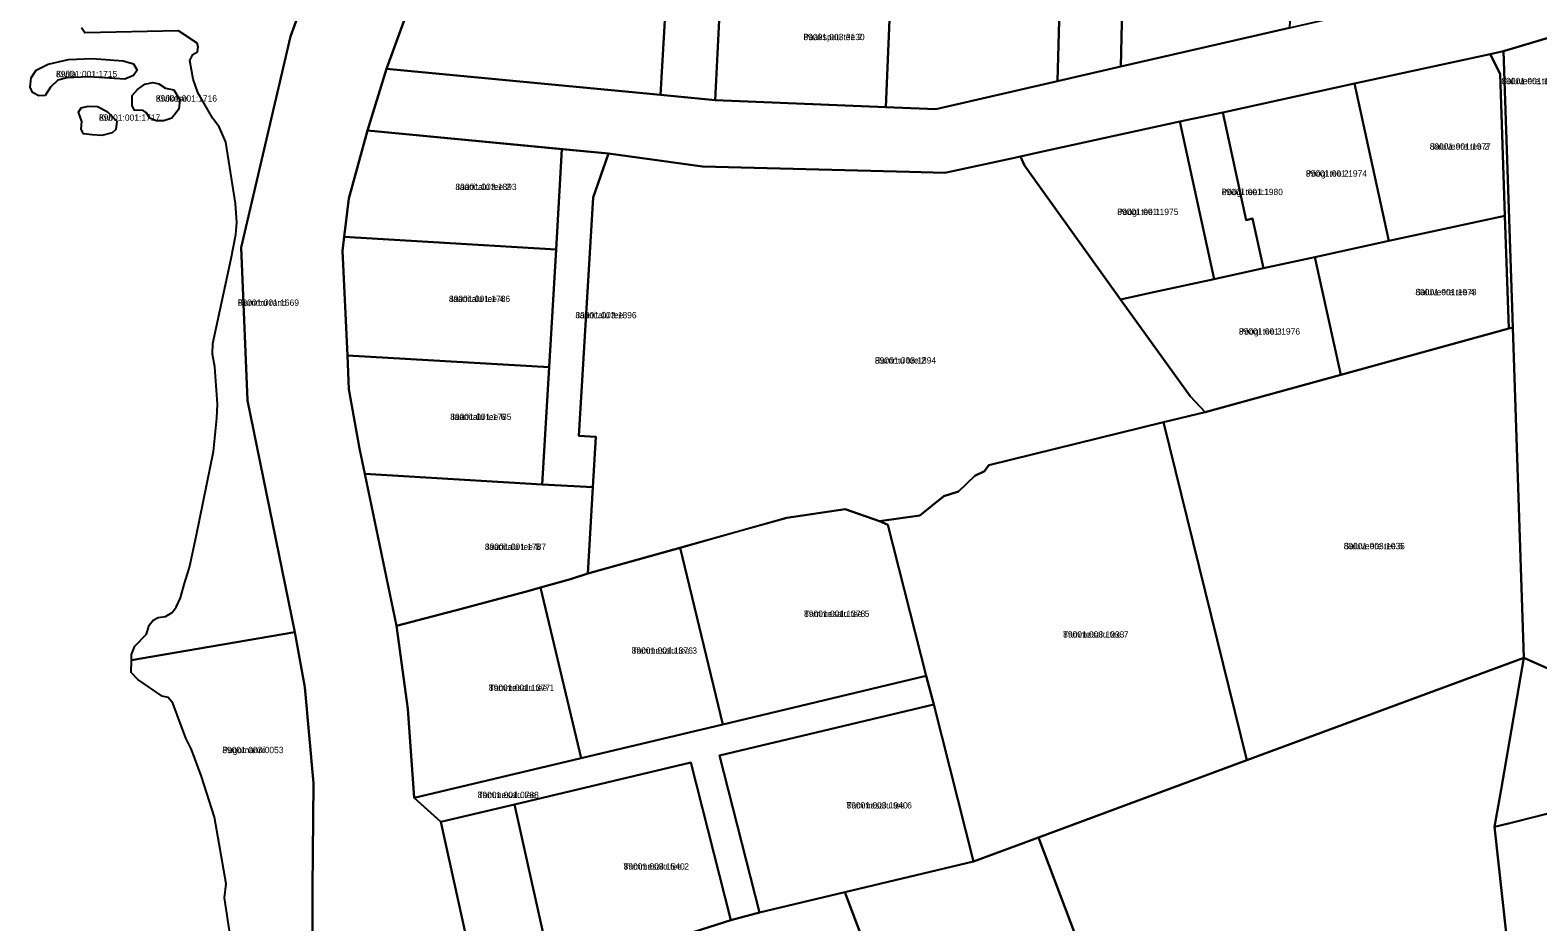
# Model space of a CAD drawing. Extents: x 526849 to 562296, y 6591741 to 6618546.
# Drawn here: x 544809.7 to 545167, y 6599914.9 to 6600126.2 of the extents above; entities that cross this region are included whole.
import ezdxf

# ---------------------------------------------------------------- set-up
doc = ezdxf.new("R2010")
doc.units = 0
for name, color, linetype in [('L_AADRESS', 7, 'Continuous'), ('PIIR', 7, 'Continuous'), ('TUNNUS', 7, 'Continuous')]:
    doc.layers.add(name, color=color, linetype=linetype)

msp = doc.modelspace()

# ---------------------------------------------------------------- linework, layer by layer
at = {"layer": 'PIIR'}
for points in [[(544935.9, 6600383.02), (544936.98, 6600367.84), (544936.01, 6600333.58), (544927.16, 6600282.9), (544924.54, 6600267.87), (544924.07, 6600264.18), (544923.97, 6600229.25), (544922.74, 6600211.91), (544921.23, 6600191.36), (544905.93, 6600149.36), (544894.17, 6600117.06), (544889.67, 6600102.41), (544885.27, 6600086.32), (544884.12, 6600077.21), (544883.73, 6600073.86), (544884.89, 6600049.11), (544885.24, 6600041.15), (544887.74, 6600027.04), (544889.02, 6600021.07), (544896.56, 6599985.02), (544899.19, 6599965.34), (544900.74, 6599944.25), (544907, 6599938.56), (544916.15, 6599897.4)], [(544876.63, 6599889.78), (544876.64, 6599922.84), (544876.87, 6599947.77), (544874.78, 6599970.54), (544872.43, 6599983.5), (544861.21, 6600038.43), (544859.69, 6600074.67), (544871.4, 6600124.69), (544896.35, 6600193.26), (544898.82, 6600204.02), (544900.09, 6600216.66), (544899.91, 6600234.86), (544900.08, 6600265.75), (544903.2, 6600290.48), (544911.64, 6600322.51), (544913.02, 6600327.74), (544914.27, 6600338.7), (544913.97, 6600348.15), (544914.61, 6600362.18), (544913.58, 6600371.54), (544912.98, 6600377.11)], [(544896.35, 6600193.26), (544871.4, 6600124.69), (544859.69, 6600074.67), (544861.21, 6600038.43), (544872.43, 6599983.5), (544838.29, 6599977.71), (544833.69, 6599976.93), (544833.72, 6599978.26), (544834.51, 6599980.25), (544837.29, 6599983.1), (544837.92, 6599985.17), (544838.87, 6599986.36), (544840.06, 6599986.99), (544841.81, 6599987.23), (544843.4, 6599988.18), (544844.35, 6599989.45), (544845.38, 6599991.68), (544846.19, 6599994.86), (544847.42, 6599998.61), (544847.72, 6600000), (544849.15, 6600006.57), (544853.2, 6600026.36), (544853.96, 6600034.22), (544854.11, 6600037.56), (544853.48, 6600046.45), (544852.92, 6600049.38), (544853, 6600051.92), (544857.37, 6600072.08), (544858.48, 6600077.8), (544858.72, 6600080.58), (544858.4, 6600085.1), (544856.1, 6600099.63), (544854.51, 6600103.28), (544853, 6600105.26), (544849.43, 6600111.45), (544848.32, 6600114.55), (544847.59, 6600119.02), (544848.24, 6600120.42), (544849.35, 6600121.06), (544849.54, 6600122.2), (544849.27, 6600123.12), (544844.89, 6600126.01), (544822.68, 6600125.58), (544821.89, 6600126.77)], [(545173.74, 6600125.66), (545158.87, 6600121.22), (545155.76, 6600120.51), (545123.56, 6600113.52), (545092.36, 6600106.67), (545082.18, 6600104.51), (545049.29, 6600097.33), (545044.38, 6600096.26), (545041.16, 6600095.54), (545026.52, 6600092.35), (545018.1, 6600092.58), (544969.05, 6600093.91), (544946.8, 6600096.96), (544889.67, 6600102.41), (544894.17, 6600117.06), (544959.09, 6600110.88), (544972.03, 6600109.6), (545012.53, 6600107.93), (545024.34, 6600107.45), (545053.15, 6600114.08), (545068.19, 6600117.54), (545108.15, 6600126.72), (545160.88, 6600138.83), (545175.72, 6600145.39)], [(544857.61, 6599908.57), (544855.78, 6599920.56), (544856.18, 6599923.89), (544853.4, 6599939.69), (544850.3, 6599949.37), (544847.92, 6599955.72), (544846.57, 6599958.42), (544843.56, 6599966.75), (544842.45, 6599968.02), (544841.02, 6599968.34), (544835.22, 6599972.31), (544833.64, 6599973.98), (544833.69, 6599976.93), (544838.29, 6599977.71), (544872.43, 6599983.5), (544874.78, 6599970.54), (544876.87, 6599947.77), (544876.64, 6599922.84), (544876.63, 6599889.78)]]:
    msp.add_lwpolyline(points, dxfattribs=at)
for points in [[(544972.6, 6600265.88), (544983.04, 6600265.45), (544981.4, 6600229.66), (544979.63, 6600219.47), (544978.27, 6600219.55), (544976.21, 6600199.58), (544974.5, 6600168.56), (544973.54, 6600139.7), (544972.03, 6600109.6), (544959.09, 6600110.88), (544960.3, 6600131.26), (544961.35, 6600141.21), (544964.46, 6600170.57), (544967.18, 6600195.94), (544970.94, 6600229.71)], [(545059.58, 6600262.28), (545072.57, 6600261.74), (545071, 6600222.28), (545069.84, 6600192.45), (545069.19, 6600162.44), (545068.19, 6600117.54), (545053.15, 6600114.08), (545054.08, 6600145.79), (545055.59, 6600174.95), (545056.79, 6600203.98), (545058.23, 6600232.66)], [(545109.76, 6600160.72), (545108.15, 6600126.72), (545068.19, 6600117.54), (545069.19, 6600162.44)], [(544905.93, 6600149.36), (544961.35, 6600141.21), (544960.3, 6600131.26), (544959.09, 6600110.88), (544894.17, 6600117.06)], [(545053.15, 6600114.08), (545024.34, 6600107.45), (545012.53, 6600107.93), (545013.8, 6600138.16), (545014.33, 6600147.56), (545054.08, 6600145.79)], [(544973.54, 6600139.7), (545013.8, 6600138.16), (545012.53, 6600107.93), (544972.03, 6600109.6)], [(545158.87, 6600121.22), (545173.74, 6600125.66), (545174.9, 6600091.74), (545176.13, 6600056.08), (545177.11, 6600026.68), (545179.03, 6599970.68), (545163.73, 6599977.48), (545161.07, 6600055.74)], [(544810.28, 6600111.45), (544809.71, 6600112.65), (544809.98, 6600114.92), (544811.16, 6600116.7), (544813.95, 6600118.12), (544818.82, 6600119.25), (544824.4, 6600119.48), (544831.73, 6600118.9), (544834.18, 6600118.2), (544835.11, 6600116.7), (544834.18, 6600115.44), (544832.18, 6600114.56), (544828.48, 6600114.83), (544823.6, 6600115.15), (544818.44, 6600114.89), (544816.28, 6600114.35), (544814.52, 6600112.65), (544813.23, 6600110.71), (544811.77, 6600110.62)], [(545131.72, 6600076.29), (545123.56, 6600113.52), (545155.76, 6600120.51), (545158.06, 6600115.86), (545159.23, 6600082.23)], [(545158.06, 6600115.86), (545155.76, 6600120.51), (545158.87, 6600121.22), (545161.07, 6600055.74), (545160.11, 6600055.48), (545159.23, 6600082.23)], [(544833.88, 6600110.7), (544835.12, 6600112.15), (544836.87, 6600113.4), (544838.79, 6600113.8), (544840.17, 6600113.48), (544841.77, 6600112.44), (544843.78, 6600112.08), (544845.15, 6600109.71), (544844.96, 6600107.43), (544843.32, 6600105.34), (544841.41, 6600104.71), (544839.59, 6600104.71), (544838.08, 6600105.34), (544837.21, 6600106.68), (544836.46, 6600107.18), (544834.43, 6600107.25), (544833.87, 6600108.25)], [(545097.9, 6600081.19), (545092.36, 6600106.67), (545123.56, 6600113.52), (545131.72, 6600076.29), (545114.14, 6600072.43), (545102.02, 6600069.8), (545099.42, 6600081.55)], [(544828, 6600106.93), (544830.22, 6600104.63), (544829.98, 6600102.64), (544829.11, 6600101.85), (544826.73, 6600101.21), (544824.43, 6600101.37), (544822.38, 6600101.61), (544821.83, 6600102.69), (544821.97, 6600104.55), (544821.17, 6600106.77), (544821.81, 6600107.8), (544823.48, 6600108.2), (544825.7, 6600108.12)], [(545045.39, 6600094.12), (545044.38, 6600096.26), (545049.29, 6600097.33), (545082.18, 6600104.51), (545090.29, 6600067.18), (545076.33, 6600064.17), (545068.14, 6600062.4)], [(545090.29, 6600067.18), (545082.18, 6600104.51), (545092.36, 6600106.67), (545097.9, 6600081.19), (545099.42, 6600081.55), (545102.02, 6600069.8)], [(544889.67, 6600102.41), (544935.74, 6600098.02), (544934.35, 6600074.23), (544884.12, 6600077.21), (544885.27, 6600086.32)], [(544935.74, 6600098.02), (544946.8, 6600096.96), (544943.12, 6600086.51), (544939.77, 6600030.06), (544943.76, 6600029.83), (544943.06, 6600017.87), (544931.08, 6600018.55), (544932.74, 6600046.33), (544934.35, 6600074.23)], [(544946.8, 6600096.96), (544969.05, 6600093.91), (545018.1, 6600092.58), (545026.52, 6600092.35), (545041.16, 6600095.54), (545044.38, 6600096.26), (545045.39, 6600094.12), (545068.14, 6600062.4), (545084.6, 6600039.45), (545088.16, 6600035.68), (545078.29, 6600033.29), (545036.92, 6600023.1), (545035.88, 6600021.65), (545033.59, 6600020.62), (545029.7, 6600016.84), (545026.23, 6600015.78), (545020.57, 6600011.2), (545011.01, 6600009.83), (545002.86, 6600012.65), (544989.06, 6600010.64), (544977.25, 6600007.35), (544941.84, 6599997.41), (544943.06, 6600017.87), (544943.76, 6600029.83), (544939.77, 6600030.06), (544943.12, 6600086.51)], [(545120.32, 6600044.52), (545114.14, 6600072.43), (545131.72, 6600076.29), (545159.23, 6600082.23), (545160.11, 6600055.48)], [(544883.73, 6600073.86), (544884.12, 6600077.21), (544934.35, 6600074.23), (544932.74, 6600046.33), (544884.89, 6600049.11)], [(545084.6, 6600039.45), (545068.14, 6600062.4), (545076.33, 6600064.17), (545090.29, 6600067.18), (545102.02, 6600069.8), (545114.14, 6600072.43), (545120.32, 6600044.52), (545088.16, 6600035.68)], [(545098.04, 6599953.21), (545078.29, 6600033.29), (545088.16, 6600035.68), (545120.32, 6600044.52), (545160.11, 6600055.48), (545161.07, 6600055.74), (545163.73, 6599977.48)], [(544885.24, 6600041.15), (544884.89, 6600049.11), (544932.74, 6600046.33), (544931.08, 6600018.55), (544889.02, 6600021.07), (544887.74, 6600027.04)], [(545011.01, 6600009.83), (545020.57, 6600011.2), (545026.23, 6600015.78), (545029.7, 6600016.84), (545033.59, 6600020.62), (545035.88, 6600021.65), (545036.92, 6600023.1), (545078.29, 6600033.29), (545098.04, 6599953.21), (545048.68, 6599934.92), (545033.29, 6599929.2), (545023.84, 6599966.37), (545022.08, 6599973.18), (545012.98, 6600008.97)], [(544896.56, 6599985.02), (544889.02, 6600021.07), (544931.08, 6600018.55), (544943.06, 6600017.87), (544941.84, 6599997.41), (544937.79, 6599996.12), (544930.63, 6599994.14), (544928.23, 6599993.4), (544911.93, 6599989.08)], [(544973.89, 6599961.68), (544963.75, 6600003.56), (544977.25, 6600007.36), (544989.06, 6600010.64), (545002.86, 6600012.65), (545011.01, 6600009.83), (545012.98, 6600008.97), (545022.08, 6599973.18)], [(544940.27, 6599953.66), (544930.63, 6599994.14), (544937.79, 6599996.12), (544941.84, 6599997.41), (544963.75, 6600003.56), (544973.89, 6599961.68)], [(545163.73, 6599977.48), (545179.03, 6599970.68), (545209.11, 6599978.82), (545238.57, 6599986.81), (545286.6, 6599999.81), (545305.47, 6600004.91), (545311.04, 6599975.66), (545278.78, 6599967.84), (545237.86, 6599957.57), (545198.15, 6599947.78), (545173.86, 6599941.68), (545160.35, 6599938.29), (545156.74, 6599937.39), (545158.3, 6599946.25)], [(544899.19, 6599965.34), (544896.56, 6599985.02), (544911.93, 6599989.08), (544928.23, 6599993.4), (544930.63, 6599994.14), (544940.27, 6599953.66), (544900.74, 6599944.25)], [(545048.68, 6599934.92), (545098.04, 6599953.21), (545163.73, 6599977.48), (545158.3, 6599946.25), (545156.74, 6599937.39), (545160.42, 6599904.41), (545163.99, 6599869.22), (545161.45, 6599868.56), (545081.67, 6599847.54)], [(544900.74, 6599944.25), (544940.27, 6599953.66), (544973.89, 6599961.68), (545022.08, 6599973.18), (545023.84, 6599966.37), (544973.07, 6599954.3), (544982.54, 6599917.15), (544975.8, 6599915.26), (544966.29, 6599952.67), (544924.51, 6599942.73), (544907, 6599938.56)], [(545023.84, 6599966.37), (545033.29, 6599929.2), (545002.78, 6599921.96), (544982.54, 6599917.15), (544973.07, 6599954.3)], [(544924.51, 6599942.73), (544966.29, 6599952.67), (544975.8, 6599915.26), (544933.6, 6599901.88)], [(545162.53, 6599904.57), (545160.42, 6599904.41), (545156.74, 6599937.38), (545160.36, 6599938.3), (545173.85, 6599941.7), (545198.15, 6599947.78), (545200.27, 6599938.7), (545203.83, 6599924.23), (545202.98, 6599911.58), (545175.09, 6599906.71)], [(544916.15, 6599897.4), (544907, 6599938.56), (544924.51, 6599942.73), (544933.6, 6599901.88), (544931.26, 6599901), (544929.8, 6599900.53), (544918.55, 6599897.89), (544921.36, 6599885.81), (544917.9, 6599884.75), (544919.81, 6599874.06), (544919.82, 6599871.95), (544934.83, 6599839.1), (544920.65, 6599833.6), (544910.88, 6599852.47), (544904.1, 6599849.41), (544900.98, 6599856.98), (544903.72, 6599858.18), (544902.51, 6599867.16), (544901.34, 6599894.22)], [(545002.78, 6599921.96), (545033.29, 6599929.2), (545048.68, 6599934.92), (545081.67, 6599847.54), (545055.54, 6599840.63), (545050.31, 6599868.18), (545049.26, 6599873.69), (545023.71, 6599866.51)], [(544931.26, 6599901), (544933.6, 6599901.88), (544975.8, 6599915.26), (544982.54, 6599917.15), (545002.78, 6599921.96), (545023.71, 6599866.51), (544977.36, 6599849.1), (544967.71, 6599875.42), (544948.56, 6599868.17), (544947.71, 6599869.8), (544943.71, 6599867.95), (544940.44, 6599876.12), (544940.94, 6599876.35)]]:
    msp.add_lwpolyline(points, close=True, dxfattribs=at)

# ---------------------------------------------------------------- texts
at = {"layer": 'L_AADRESS'}
for s, p in [('Paakspuu tee 2', (544992.97, 6600123.82)), ('Kivila', (544815.84, 6600115.05)), ('Saluveere tee L2', (545158.41, 6600113.39)), ('Kivikese', (544839.49, 6600109.26)), ('Kivi', (544826.03, 6600104.71)), ('Saluveere tee 2', (545141.39, 6600097.89)), ('Pöögi tee 2', (545112.04, 6600091.48)), ('Jaanitalu tee 2', (544910.5, 6600088.32)), ('Pöögi tee L1', (545092.1, 6600087.1)), ('Pöögi tee 1', (545067.34, 6600082.4)), ('Saluveere tee 4', (545138, 6600063.38)), ('Rummu rand', (544858.92, 6600060.87)), ('Jaanitalu tee 4', (544908.96, 6600061.77)), ('Jaanitalu tee', (544938.94, 6600057.91)), ('Pöögi tee 3', (545096.17, 6600054.05)), ('Rummu tee 2', (545009.92, 6600047.19)), ('Jaanitalu tee 6', (544909.27, 6600033.83)), ('Jaanitalu tee 8', (544917.48, 6600003.04)), ('Saluveere tee 6', (545121.01, 6600003.2)), ('Tammesalu tee 5', (544993.12, 6599987.16)), ('Tammesalu tee 7', (545054.52, 6599982.26)), ('Tammesalu tee 3', (544952.26, 6599978.43)), ('Tammesalu tee 1', (544918.42, 6599969.63)), ('Pugomanni', (544855.25, 6599954.87)), ('Tammesalu tee', (544915.77, 6599944.22)), ('Tammesalu tee 6', (545003.18, 6599941.76)), ('Tammesalu tee 2', (544950.35, 6599927.28))]:
    msp.add_text(s, height=1.5, dxfattribs=at).set_placement(p)
at = {"layer": 'TUNNUS'}
for s, p in [('89001:003:3130', (544992.97, 6600123.82)), ('89001:001:1715', (544815.84, 6600115.05)), ('89001:001:1979', (545158.41, 6600113.39)), ('89001:001:1716', (544839.49, 6600109.26)), ('89001:001:1717', (544826.03, 6600104.71)), ('89001:001:1977', (545141.39, 6600097.89)), ('89001:001:1974', (545112.04, 6600091.48)), ('89001:003:1893', (544910.5, 6600088.32)), ('89001:001:1980', (545092.1, 6600087.1)), ('89001:001:1975', (545067.34, 6600082.4)), ('89001:001:1978', (545138, 6600063.38)), ('89001:001:1669', (544858.92, 6600060.87)), ('89001:001:1786', (544908.96, 6600061.77)), ('89001:003:1896', (544938.94, 6600057.91)), ('89001:001:1976', (545096.17, 6600054.05)), ('89001:003:1894', (545009.92, 6600047.19)), ('89001:001:1785', (544909.27, 6600033.83)), ('89001:001:1787', (544917.48, 6600003.04)), ('89001:003:1036', (545121.01, 6600003.2)), ('89001:001:1378', (544993.12, 6599987.16)), ('89001:003:1033', (545054.52, 6599982.26)), ('89001:001:1376', (544952.26, 6599978.43)), ('89001:001:1377', (544918.42, 6599969.63)), ('89001:003:0053', (544855.25, 6599954.87)), ('89001:001:0788', (544915.77, 6599944.22)), ('89001:003:1940', (545003.18, 6599941.76)), ('89001:003:1540', (544950.35, 6599927.28))]:
    msp.add_text(s, height=1.5, dxfattribs=at).set_placement(p)

doc.saveas('drawing.dxf')
